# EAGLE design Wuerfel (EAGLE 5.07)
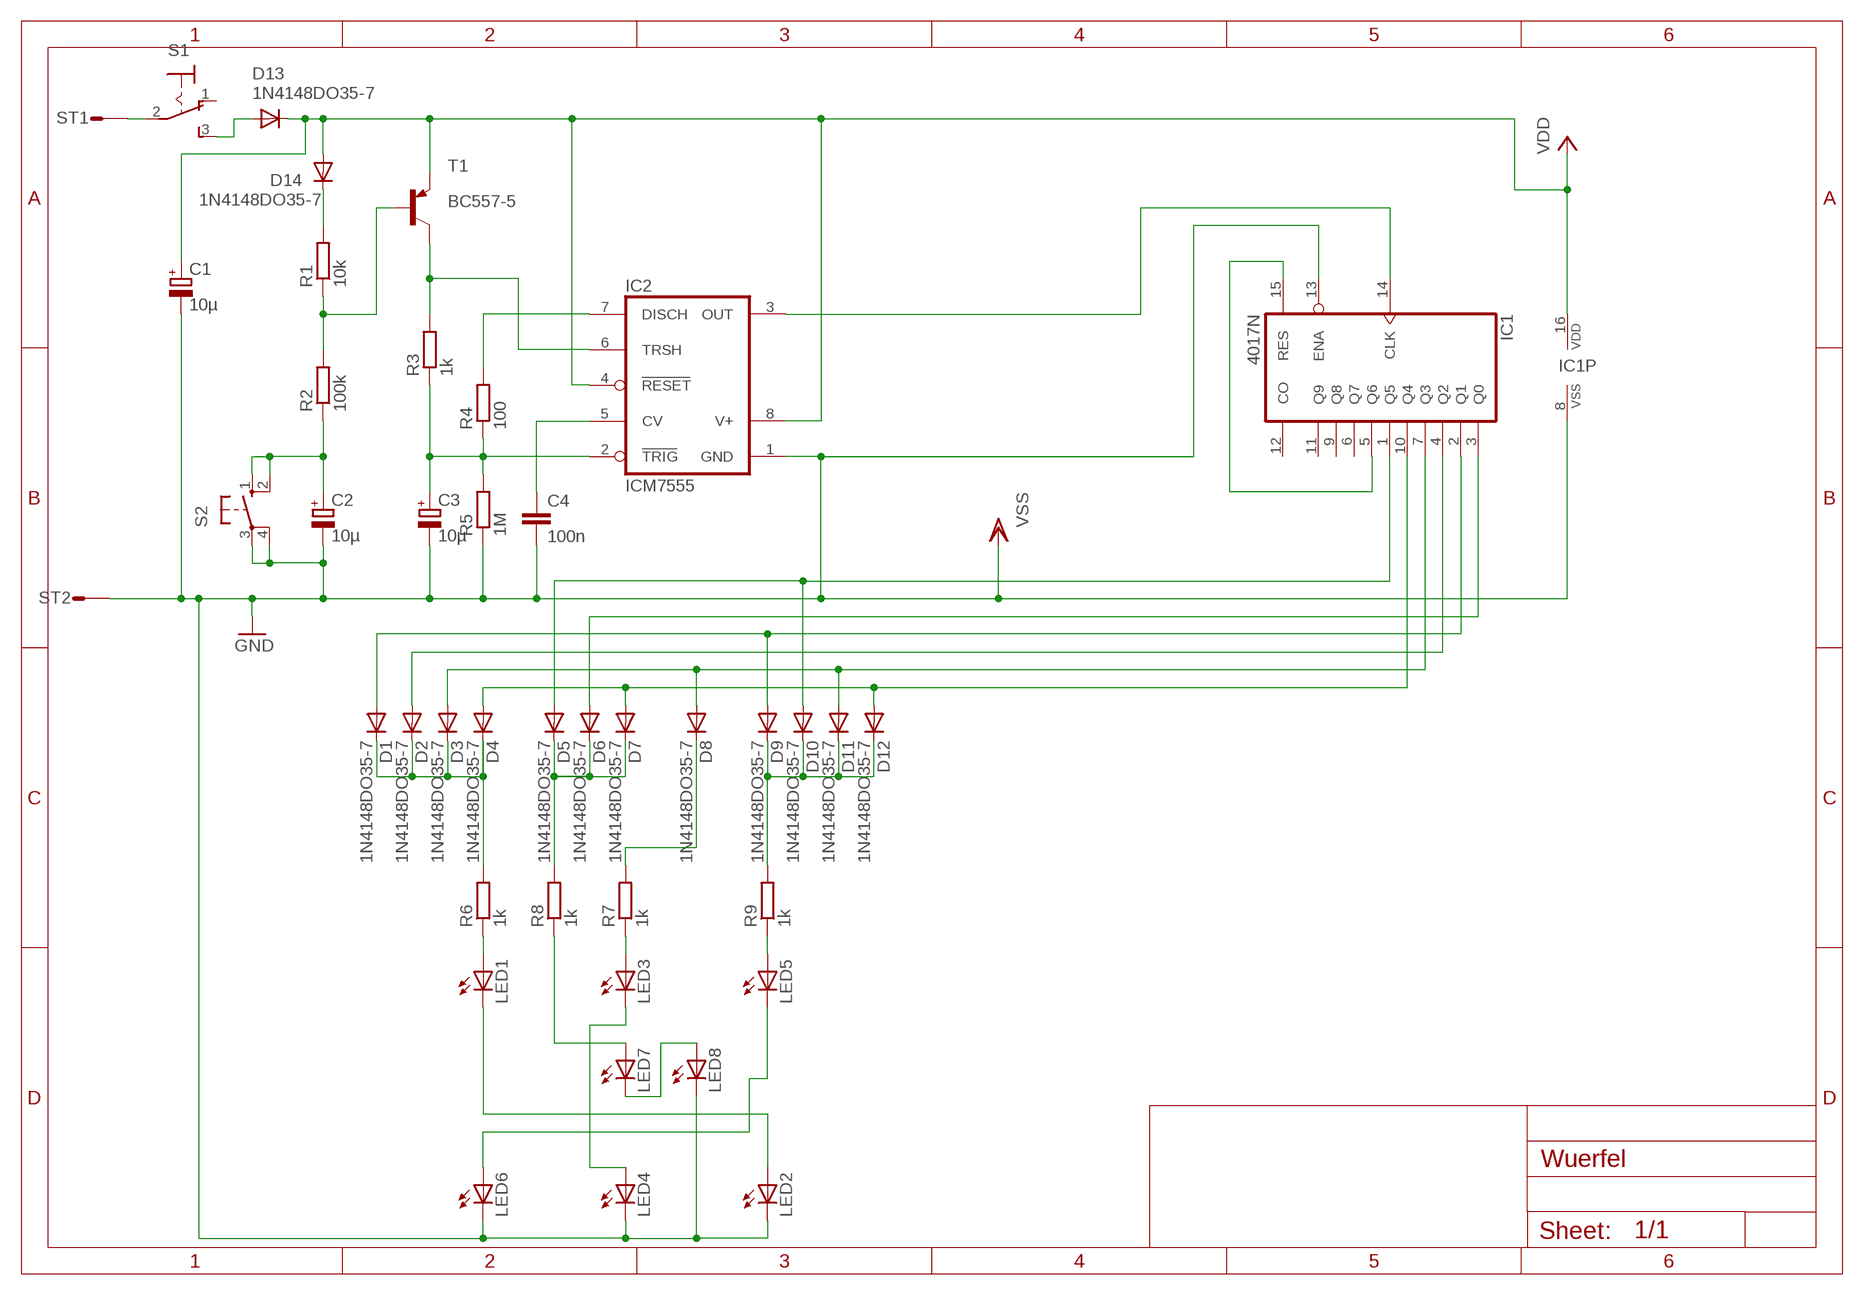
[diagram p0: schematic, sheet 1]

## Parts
C1  10µ  CPOL-EUE2,5-6E  [E2,5-6E]
C2  10µ  CPOL-EUE2,5-6E  [E2,5-6E]
C3  10µ  CPOL-EUE2,5-6E  [E2,5-6E]
C4  100n  C-EU025-025X050  [C025-025X050]
D1  1N4148DO35-7  [DO35-7]
D2  1N4148DO35-7  [DO35-7]
D3  1N4148DO35-7  [DO35-7]
D4  1N4148DO35-7  [DO35-7]
D5  1N4148DO35-7  [DO35-7]
D6  1N4148DO35-7  [DO35-7]
D7  1N4148DO35-7  [DO35-7]
D8  1N4148DO35-7  [DO35-7]
D9  1N4148DO35-7  [DO35-7]
D10  1N4148DO35-7  [DO35-7]
D11  1N4148DO35-7  [DO35-7]
D12  1N4148DO35-7  [DO35-7]
D13  1N4148DO35-7  [DO35-7]
D14  1N4148DO35-7  [DO35-7]
IC1  4017N  [DIL16]
IC2  ICM7555  [DIL08]
LED1  LED3MM  [LED3MM]
LED2  LED3MM  [LED3MM]
LED3  LED3MM  [LED3MM]
LED4  LED3MM  [LED3MM]
LED5  LED3MM  [LED3MM]
LED6  LED3MM  [LED3MM]
LED7  LED3MM  [LED3MM]
LED8  LED5MM  [LED5MM]
R1  10k  R-EU_0204/7  [0204/7]
R2  100k  R-EU_0204/7  [0204/7]
R3  1k  R-EU_0204/7  [0204/7]
R4  100  R-EU_0204/7  [0204/7]
R5  1M  R-EU_0204/7  [0204/7]
R6  1k  R-EU_0204/7  [0204/7]
R7  1k  R-EU_0204/7  [0204/7]
R8  1k  R-EU_0204/7  [0204/7]
R9  1k  R-EU_0204/7  [0204/7]
S1  320-916  [320-916]
S2  10-XX  [B3F-10XX]
ST1  ST2,8  [ST2,8]
ST2  ST2,8  [ST2,8]
T1  BC557-5  [TO92-5]

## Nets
GND: C1.- C2.- C3.- C4.2 IC1.8(VSS) IC1.13(ENA) IC2.1(GND) LED2.K(C) LED4.K(C) LED6.K(C) LED8.K(C) R5.1 S2.3(P) S2.4(P1) ST2.1(ST) ; supply symbol labelled VSS
N$1: S1.2(P) ST1.1(ST)
N$3: IC2.6(TRSH) R3.2 T1.3(C)
N$5: D14.C R1.2
N$6: R1.1 R2.2 T1.2(B)
N$7: C2.+ R2.1 S2.1(S) S2.2(S1)
N$8: IC2.7(DISCH) R4.2
N$9: C3.+ IC2.2(TRIG) R3.1 R4.1 R5.2
N$10: D8.C R7.2
N$11: D1.C D2.C D3.C D4.C R6.2
N$12: LED1.A R6.1
N$13: D5.C D6.C D7.C R8.2
N$14: LED7.A R8.1
N$16: LED3.A R7.1
N$17: LED3.K(C) LED4.A
N$18: LED7.K(C) LED8.A
N$19: LED1.K(C) LED2.A
N$20: LED5.K(C) LED6.A
N$21: LED5.A R9.1
N$22: D9.C D10.C D11.C D12.C R9.2
N$23: D4.A D7.A D12.A IC1.10(Q4)
N$24: D3.A D8.A D11.A IC1.7(Q3)
N$25: D2.A IC1.4(Q2)
N$26: D1.A D9.A IC1.2(Q1)
N$27: D6.A IC1.3(Q0)
N$28: D5.A D10.A IC1.1(Q5)
N$29: IC1.5(Q6) IC1.15(RES)
N$30: IC1.14(CLK) IC2.3(OUT)
N$32: D13.A S1.3(S)
N$35: C4.1 IC2.5(CV)
VCC: C1.+ D13.C D14.A IC1.16(VDD) IC2.4(RESET) IC2.8(V+) T1.1(E) ; supply symbol labelled VDD
Unconnected: IC1.6(Q7) IC1.9(Q8) IC1.11(Q9) IC1.12(CO) S1.1(O)

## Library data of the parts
C1-C3 = resistor:CPOL-EU: POLARIZED CAPACITOR, European symbol
C4 = rcl:C-EU: CAPACITOR, European symbol
D1-D14 = diode:1N4148: DIODE
IC1 = 40xx:4017: COUNTER/DIVIDER
IC2 = maxim:ICM7555: TIMER
LED1-LED8 = led:LED: LED
R1-R9 = resistor:R-EU_: RESISTOR, European symbol
S1 = switch:320-916: TOGGLE SWITCH distributor RS Components
S2 = switch-omron:10-XX: OMRON SWITCH
ST1 ST2 = con-rib:ST2,8: RIBBON CABLE CONNECTOR
T1 = armin:BC557: PNP Transistor

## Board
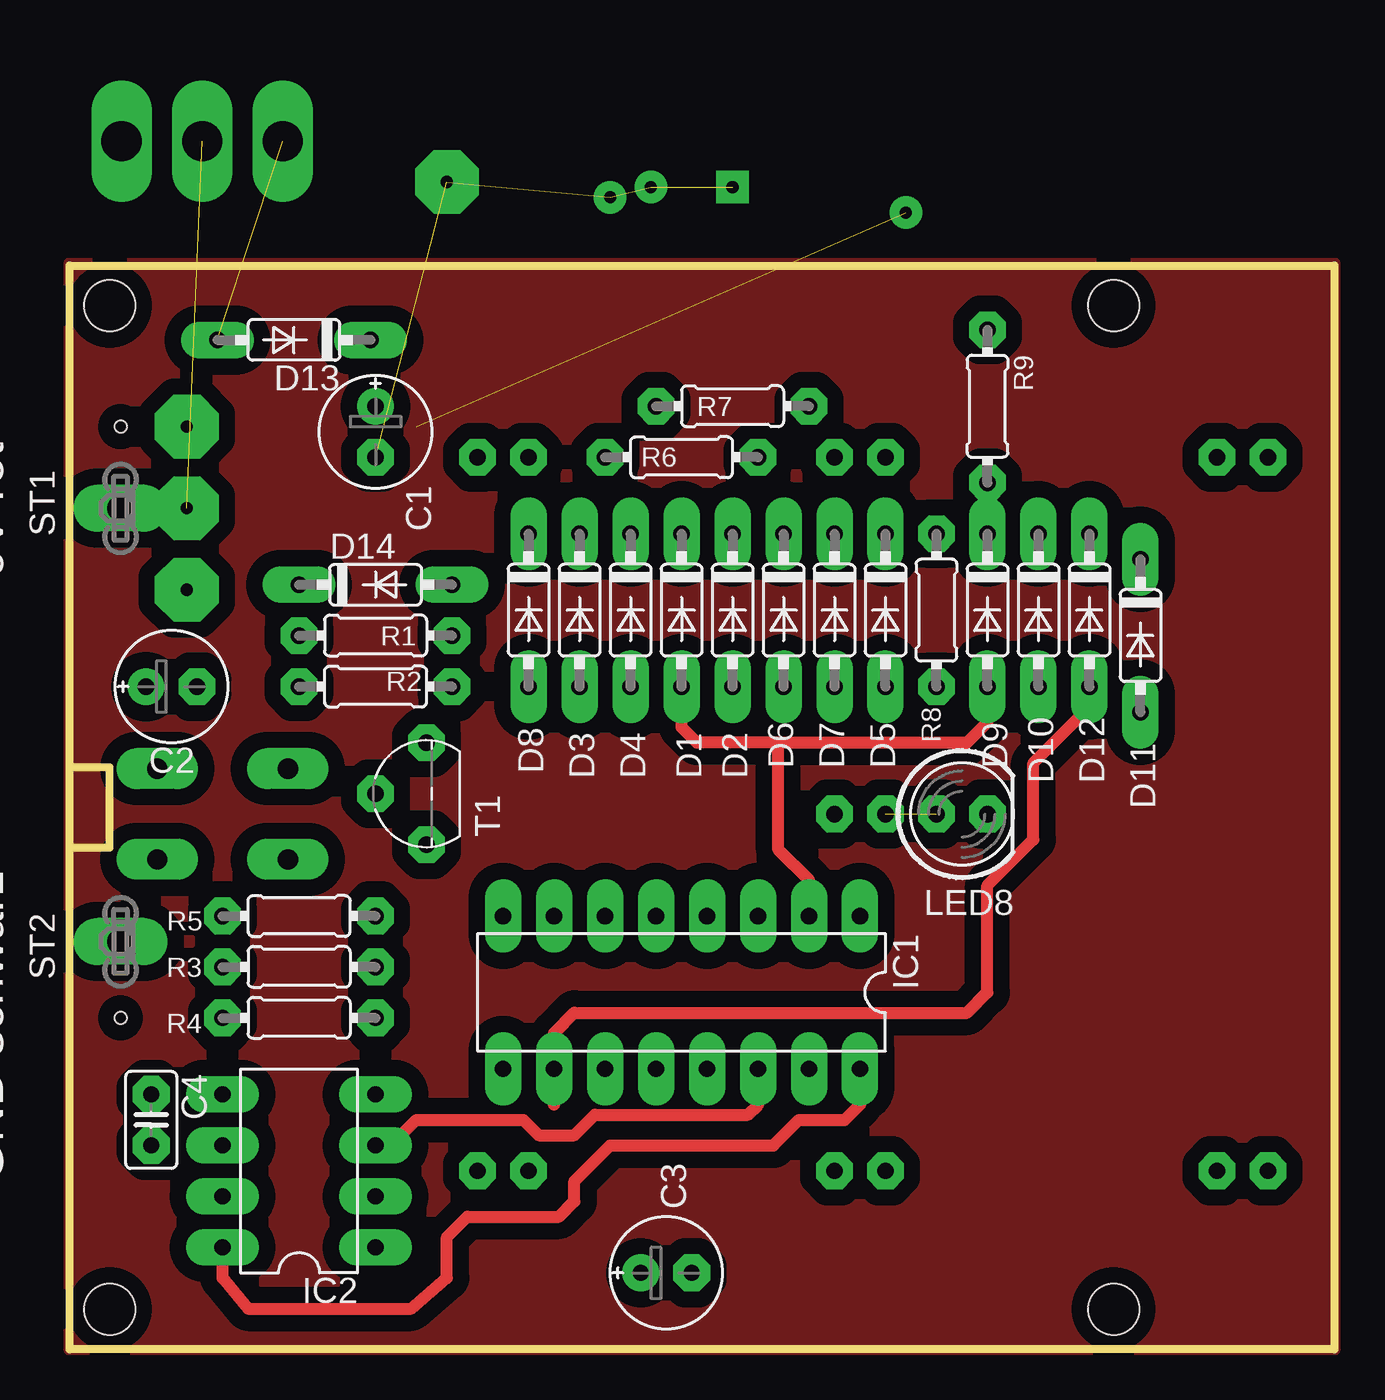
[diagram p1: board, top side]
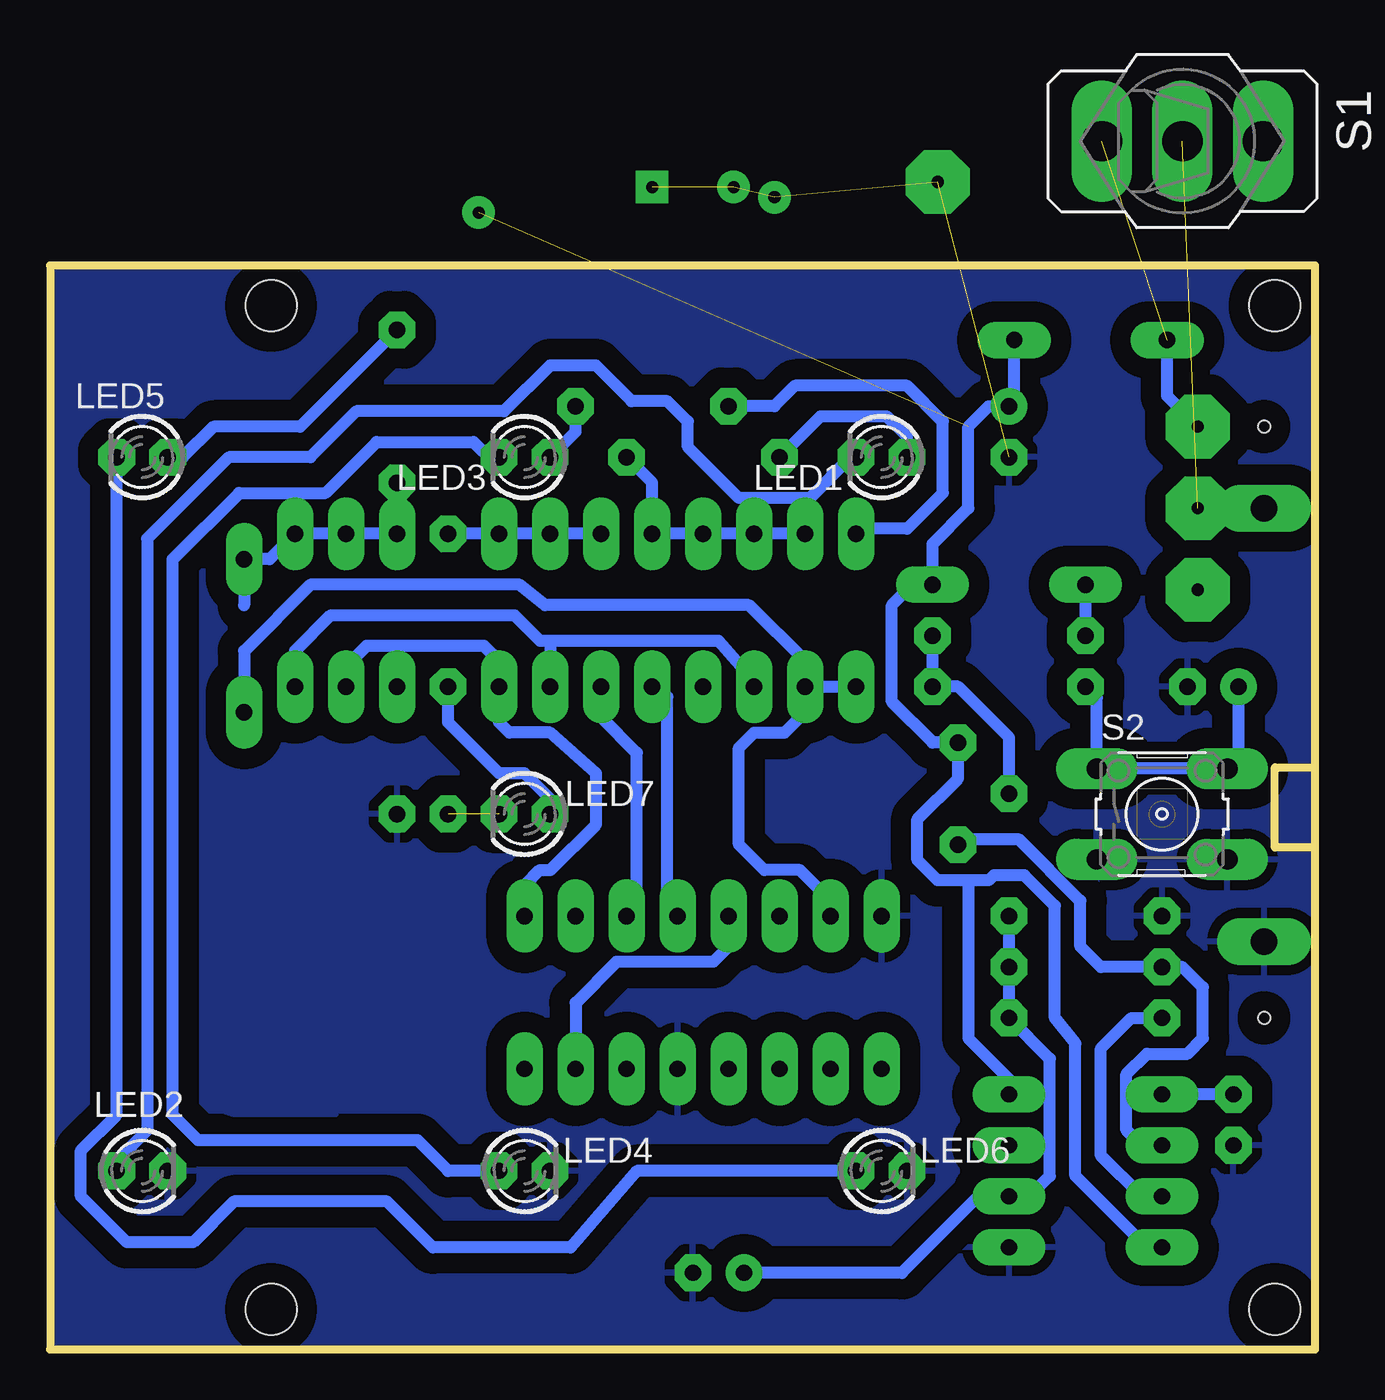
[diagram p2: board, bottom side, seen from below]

Size 63 x 54 mm. Coordinates in mm from the lower left corner, seen from the top.
Outline: 0,25 0,0 63,0 63,54 0,54 0,29
Outline: 0,25 0,29
Outline: 0,25 2,25 2,29 0,29
Copper layers (1*16): Top 0.035mm / dielectric 1.5mm / Bottom 0.035mm
Design rules "default *": minimum track width 32mil, minimum drill 24mil, track to track 20mil, track to pad 20mil, pad to pad 20mil, via to via 20mil, smd to smd 8mil, copper to edge 0mil, drill to drill 8mil, minimum pad ring 20mil, minimum via ring 20mil, stop-mask expansion 4mil, vias tented up to drill 0mil, thermal gap 20mil
Holes 2.54 mm at 2,2 2,52 52,2 52,52
Holes 0.6 mm at 2.54,16.51 2.54,45.97
tKeepout: area 0,36 to 7,54

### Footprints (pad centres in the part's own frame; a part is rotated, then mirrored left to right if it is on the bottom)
E2,5-6E = drill 0.813 pad 1.575 round: + -1.27,0 | drill 0.813 pad 1.575 octagon: - 1.27,0
C025-025X050 = drill 0.813 octagon: 1 -1.27,0; 2 1.27,0
DO35-7 = drill 0.813 long: A 3.81,0; C -3.81,0
DIL16 = drill 0.813 long: 1 -8.89,-3.81; 2 -6.35,-3.81; 3 -3.81,-3.81; 4 -1.27,-3.81; 5 1.27,-3.81; 6 3.81,-3.81; 7 6.35,-3.81; 8 8.89,-3.81; 9 8.89,3.81; 10 6.35,3.81; 11 3.81,3.81; 12 1.27,3.81; 13 -1.27,3.81; 14 -3.81,3.81; 15 -6.35,3.81; 16 -8.89,3.81
DIL08 = drill 0.813 long: 1 -3.81,-3.81; 2 -1.27,-3.81; 3 1.27,-3.81; 4 3.81,-3.81; 5 3.81,3.81; 6 1.27,3.81; 7 -1.27,3.81; 8 -3.81,3.81
LED3MM = drill 0.813 octagon: A -1.27,0; K 1.27,0
LED5MM = drill 0.813 octagon: A -1.27,0; K 1.27,0
0204/7 = drill 0.813 octagon: 1 -3.81,0; 2 3.81,0
320-916 = drill 2.007 long: 1 0,4.013; 2 0,0; 3 0,-4.013
B3F-10XX = drill 1.016 long: 1 -3.251,2.261; 2 3.251,2.261; 3 -3.251,-2.261; 4 3.251,-2.261
ST2,8 = drill 1.321 long: 1 0,0
TO92-5 = drill 0.813 octagon: 1 2.54,0; 2 0,2.54; 3 -2.54,0

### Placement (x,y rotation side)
C1  15.24,45.72 270 top
C2  5.08,33.02 0 top
C3  29.72,3.81 0 top
C4  4.06,11.43 270 top
D1  30.48,36.83 270 top
D2  33.02,36.83 270 top
D3  25.4,36.83 270 top
D4  27.94,36.83 270 top
D5  40.64,36.83 270 top
D6  35.56,36.83 270 top
D7  38.1,36.83 270 top
D8  22.86,36.83 270 top
D9  45.72,36.83 270 top
D10  48.26,36.83 270 top
D11  53.34,35.56 270 top
D12  50.8,36.83 270 top
D13  11.18,50.29 180 top
D14  15.24,38.1 0 top
IC1  30.48,17.78 180 top
IC2  11.43,8.89 90 top
LED1  21.59,44.45 180 bottom
LED2  58.42,8.89 0 bottom
LED3  39.37,44.45 180 bottom
LED4  39.37,8.89 0 bottom
LED5  58.42,44.45 180 bottom
LED6  21.59,8.89 0 bottom
LED7  39.37,26.67 180 bottom
LED8  44.45,26.67 0 top
R1  15.24,35.56 180 top
R2  15.24,33.02 0 top
R3  11.43,19.05 180 top
R4  11.43,16.51 180 top
R5  11.43,21.59 0 top
R6  30.48,44.45 0 top
R7  33.02,46.99 180 top
R8  43.18,36.83 90 top
R9  45.72,46.99 270 top
S1  not placed on the board
S2  7.62,26.67 0 bottom
ST1  2.54,41.91 90 top
ST2  2.54,20.32 90 top
T1  17.78,27.69 90 top

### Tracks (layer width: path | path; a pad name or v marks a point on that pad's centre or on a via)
GND  (via drill 0.6, 0.6 pad 0.3, 0.6 pad 3.17)  (4 unrouted)
  other vias: 33.02,57.91 28.96,57.91 26.92,57.4 18.8,58.17
  pour Bottom (isolate 1.016): 0.25,53.85 62.99,53.85 62.99,0.25 62.74,0 0.25,0 0,0.25 0,53.59
  pour Bottom: 55.37,27.43 49.78,27.69 49.78,22.35 48.51,21.34 48.77,11.68 53.85,11.68 55.37,12.19
N$1  (via drill 0.6 pad 3.17)  (1 unrouted)
  Bottom 0.61: ST1.1 v5.84,41.91
N$2  (via drill 0.6)
  other vias: 52,2
N$3
  Bottom 0.61: IC2.6 8.64,10.16 9.4,10.92 9.4,13.72 8.38,14.73 6.35,14.73 5.59,15.49 5.59,18.03 6.6,19.05 R3.2 10.67,19.05 11.68,20.07 11.68,22.35 14.73,25.4 17.53,25.4 T1.3 17.53,24.89
N$4  (via drill 0.6)
  other vias: 52,52
N$5
  Bottom 0.61: R1.2 D14.C
N$6
  Bottom 0.61: R1.1 R2.2 17.78,33.02 15.24,30.48 T1.2
N$7
  Bottom 0.61: C2.+ 3.81,29.49 S2.2 S2.1 10.87,32.46 R2.1
N$8
  Bottom 0.61: IC2.7 8.64,7.62 10.67,9.65 10.67,14.99 9.14,16.51 R4.2
N$9
  Bottom 0.61: R4.1 R3.1 | R4.1 R5.2 | C3.+ 20.57,3.81 16.76,7.62 IC2.2 14.22,7.62 13.21,8.64 13.21,14.48 R4.1
N$10
  Bottom 0.61: D8.C 22.61,40.89 20.32,40.89 18.54,42.67 18.54,46.23 20.32,48.01 25.91,48.01 26.92,46.99 R7.2
N$11
  Bottom 0.61: D3.C D4.C D1.C D2.C 33.02,43.18 R6.2
N$12
  Bottom 0.61: LED1.A 20.32,45.47 21.34,46.48 24.64,46.48 R6.1
N$13
  Bottom 0.61: D6.C D7.C | D7.C D5.C | D5.C R8.2 D5.C | D7.C D5.C
N$14
  Bottom 0.61: R8.1 43.18,31.24 40.64,28.7 39.37,28.7 38.1,27.43 LED7.A
N$15  (via drill 0.6)
  other vias: 2,52
N$16
  Bottom 0.61: R7.1 36.83,45.72 LED3.A
N$17
  Bottom 0.61: LED4.A 43.18,8.89 44.7,10.41 55.63,10.41 56.9,11.68 56.9,39.37 53.59,42.67 49.28,42.67 46.74,45.21 41.91,45.21 40.89,44.2 LED3.K
N$18  (1 unrouted)
N$19
  Bottom 0.61: LED2.A 59.69,9.4 58.17,10.92 58.17,40.39 54.1,44.45 50.04,44.45 47.75,46.74 40.39,46.74 38.1,49.02 35.81,49.02 34.04,47.24 32.26,47.24 31.24,46.23 31.24,44.96 28.7,42.42 25.15,42.42 23.11,44.45 LED1.K 22.86,44.7
N$20
  Bottom 0.61: 22.86,8.64 LED6.A 33.78,8.89 37.08,5.08 43.94,5.08 46.23,7.37 53.85,7.37 55.88,5.33 59.18,5.33 61.47,7.62 61.47,9.91 59.69,11.68 LED5.K
N$21
  Bottom 0.61: LED5.A 56.39,44.45 54.86,45.97 50.55,45.97 R9.1
N$22
  Bottom 0.61: R9.2 D9.C D10.C D12.C 52.07,39.37 D11.C 53.34,37.08
N$23
  Top 0.61: 24.13,12.19 IC1.10 24.13,15.75 25.15,16.76 44.7,16.76 45.72,17.78 45.72,23.11 48.01,25.4 48.01,29.21 50.8,32 D12.A
  Bottom 0.61: 38.1,35.31 D7.A | D4.A 27.94,33.27 29.72,35.31 38.1,35.31 | D12.A 50.8,34.8 49.02,36.58 39.88,36.58 38.61,35.31 38.1,35.31
N$24
  Bottom 0.61: D3.A D8.A | D11.A 53.34,34.8 50.04,38.1 39.62,38.1 38.35,37.08 28.19,37.08 25.4,34.29 D3.A | IC1.7 24.13,22.35 25.65,23.88 27.43,23.88 28.7,25.15 28.7,29.97 27.94,30.73 26.42,30.73 25.4,31.75 D3.A
N$25
  Bottom 0.61: D2.A 33.02,33.27 32.26,32.51 32.26,22.86 31.75,22.35 IC1.4
N$26
  Top 0.61: D1.A 30.48,30.99 31.24,30.23 35.31,30.23 | 35.31,30.23 44.7,30.23 45.72,31.24 D9.A | IC1.2 36.83,23.37 35.31,24.89 35.31,30.23
N$27
  Bottom 0.61: D6.A 35.56,31.5 33.78,29.72 33.78,22.86 34.29,22.35 IC1.3
N$28
  Bottom 0.61: IC1.1 39.37,23.11 38.61,23.88 38.1,23.88 35.81,26.16 35.81,28.7 38.1,30.73 40.13,30.73 40.64,31.24 D5.A 40.64,34.29 41.4,35.05 47.24,35.05 48.26,34.04 D10.A
N$29
  Bottom 0.61: IC1.5 29.21,20.07 29.97,19.3 34.8,19.3 36.83,17.27 IC1.15
N$30
  Top 0.61: IC1.14 34.29,12.19 33.78,11.68 26.16,11.68 25.15,10.67 23.37,10.67 22.61,11.43 17.27,11.43 16,10.16 IC2.3
N$31  (via drill 0.6)
  other vias: 2,2
N$32  (via drill 0.6 pad 3.17)  (1 unrouted)
  Bottom 0.61: D13.A 7.37,47.5 v5.84,45.97
N$33
  pour Top (isolate 0.813): 0,0 0,54.1 62.99,54.1 62.99,0
N$34  (via drill 0.6 pad 3.17)
  other vias: 5.84,37.85
N$35
  Bottom 0.61: C4.1 IC2.5
VCC  (via drill 0.6 pad 1.42)  (1 unrouted)
  Top 0.61: IC1.16 39.37,12.19 38.61,11.43 36.32,11.43 35.05,10.16 26.92,10.16 25.15,8.38 25.15,7.37 24.38,6.6 19.81,6.6 18.8,5.59 18.8,3.56 17.02,2.03 8.89,2.03 7.62,3.56 IC2.8
  Bottom 0.61: IC2.8 8.38,5.08 11.94,8.64 11.94,15.24 12.95,16.51 12.95,22.1 14.48,23.62 16,23.62 16.26,23.37 17.27,23.37 | IC2.4 15.24,13.46 17.27,15.49 17.27,23.37 | 17.27,23.37 18.8,23.37 19.81,24.38 19.81,26.42 17.78,28.45 T1.1 19.05,30.23 21.08,32.26 21.08,37.08 20.07,38.1 D14.A 19.05,40.13 17.27,41.91 17.27,45.97 16.26,46.99 C1.+ 14.99,47.24 D13.C
  other vias: 41.66,56.64

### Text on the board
tPlace: +9V rot | GND schwarz
bRestrict: 002V1.2 | Würfel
